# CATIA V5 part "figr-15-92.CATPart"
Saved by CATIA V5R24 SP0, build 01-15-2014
Part number: Part1
Bounding box of the stored display mesh (mm): x -40 to 40, y -60 to 60, z 0 to 2
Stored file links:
  D:\KAVITA\CATIA V5-6R2014 Project_ Kavita\CATIA V5-6R2014_partfiles\Partfiles\c15_catia_v5-6r2014_prt\figr-15-92.CATPart
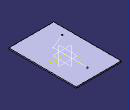
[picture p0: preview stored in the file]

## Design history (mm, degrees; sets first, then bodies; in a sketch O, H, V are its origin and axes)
SheetMetalParameters1: Thickness 2, BendRadius 4, KFactor 0.400515 {= log(min(100,max(20*SheetMetalParameters1.BendRadius,SheetMetalParameters1.Thickness)/SheetMetalParameters1.Thickness))/log(100)/2}, ReliefRadialLength 1, ReliefAxialLength 2, MinimumBendRadius 0
Body1 (main body)
  Sketch1 on xy-plane, origin (0, 0, 0), H (-1, 0, 0), V (0, -1, 0)
    line L1 (40, 60) -> (40, -60)
    line L2 (40, -60) -> (-40, -60)
    line L3 (-40, -60) -> (-40, 60)
    line L4 (-40, 60) -> (40, 60)
    length L4 = 80
    length L1 = 120
    vertical: L1 V, L3 V
    horizontal: L2 H, L4 H
    equidistance: L1 L3 O, L2 L4 O
  Wall1: Thickness 2, Profile Sketch1, OffsetValue 0
  Sketch2 on face of Wall1, origin (0, 0, 2), H (1, 0, 0), V (0, 1, 0)
    line L1 (0, 40.0798) -> (0, -21.0085)
    line L2 (0, -21.0085) -> (-27, -32)
    vertical: L1 V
